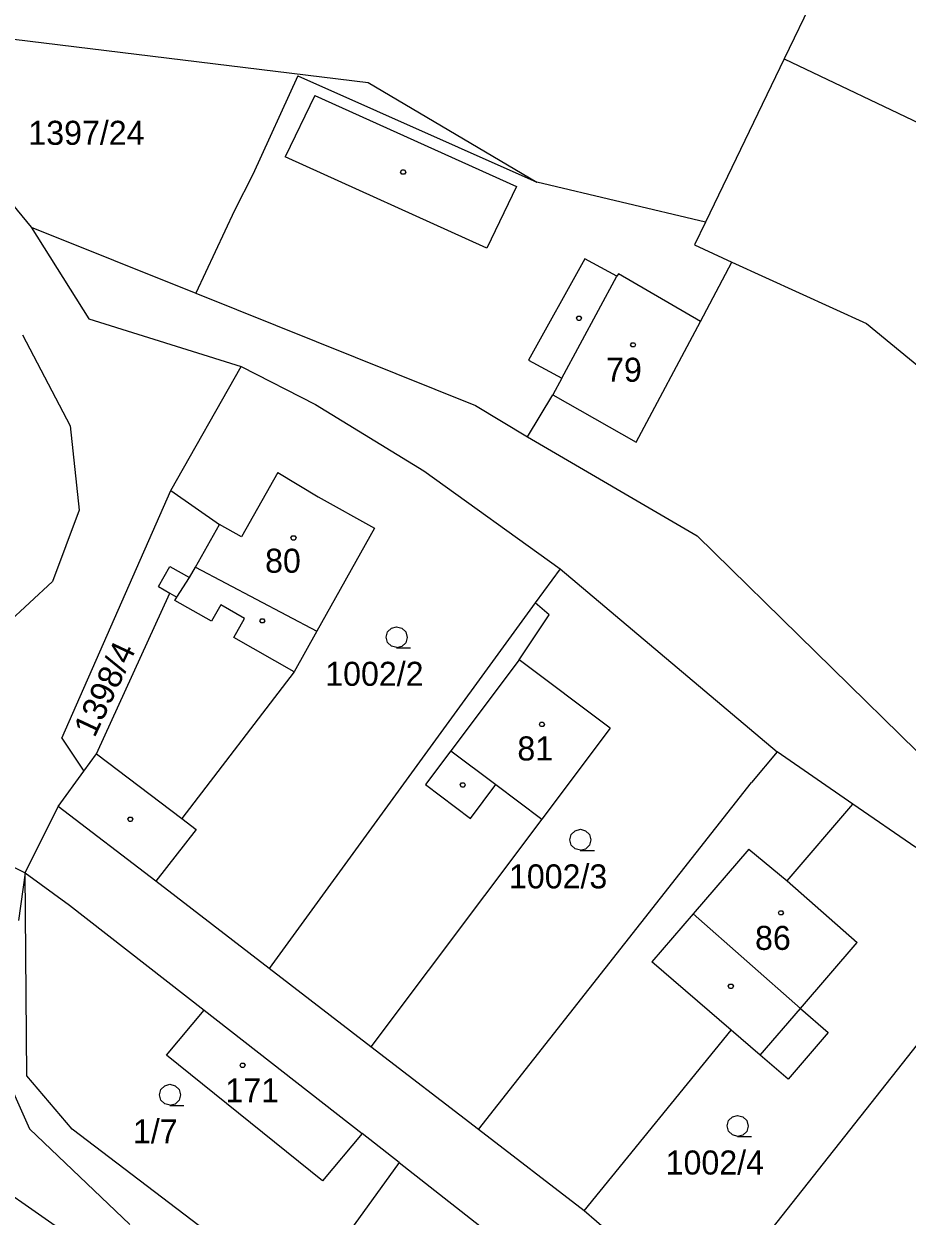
# Model space of a CAD drawing. Extents: x -852001 to -842497, y -1063614 to -1052182.
# Drawn here: x -849249.6 to -849187.1, y -1056339.7 to -1056255.4 of the extents above; entities that cross this region are included whole.
import ezdxf

# ---------------------------------------------------------------- set-up
doc = ezdxf.new("R2010")
doc.units = 0
for name, color, linetype in [('Default', 7, 'Continuous'), ('KN_HRANICE', 7, 'Continuous'), ('KN_KULTURY', 7, 'Continuous'), ('KN_PARCELY', 7, 'Continuous'), ('KN_SLUCKY', 7, 'Continuous')]:
    doc.layers.add(name, color=color, linetype=linetype)

# ---------------------------------------------------------------- blocks, each defined once
blk = doc.blocks.new('304')
at = {"layer": 'Default'}
blk.add_lwpolyline([(0, 0), (-0.38, 0.1), (-0.65, 0.37), (-0.75, 0.74), (-0.65, 1.11), (-0.38, 1.38), (-0.01, 1.48), (0.36, 1.38), (0.63, 1.11), (0.73, 0.73), (0.63, 0.35), (0.36, 0.08), (-0.02, -0.02), (0.98, -0.02)], dxfattribs=at)
blk = doc.blocks.new('402')
at = {"layer": 'Default'}
blk.add_lwpolyline([(0.09, 0.15), (0.18, 0), (0.09, -0.15), (-0.09, -0.15), (-0.18, 0), (-0.09, 0.15), (0.09, 0.15)], dxfattribs=at)

msp = doc.modelspace()

# ---------------------------------------------------------------- linework, layer by layer
at = {"layer": 'KN_HRANICE'}
for p, q in [((-849187.73, -1056241.12), (-849195.81, -1056257.87)), ((-849187.73, -1056241.12), (-849195.81, -1056257.87)), ((-849261.46, -1056255.12), (-849225.25, -1056259.54)), ((-849261.46, -1056255.12), (-849225.25, -1056259.54)), ((-849195.81, -1056257.87), (-849201.39, -1056269.43)), ((-849195.81, -1056257.87), (-849201.39, -1056269.43)), ((-849195.81, -1056257.87), (-849167.34, -1056271.45)), ((-849195.81, -1056257.87), (-849167.34, -1056271.45)), ((-849230.23, -1056259.07), (-849233.42, -1056266.05)), ((-849230.23, -1056259.07), (-849233.42, -1056266.05)), ((-849230.23, -1056259.07), (-849213.31, -1056266.59)), ((-849230.23, -1056259.07), (-849213.31, -1056266.59)), ((-849225.25, -1056259.54), (-849213.31, -1056266.59)), ((-849225.25, -1056259.54), (-849213.31, -1056266.59)), ((-849233.42, -1056266.05), (-849234.71, -1056268.6)), ((-849233.42, -1056266.05), (-849234.71, -1056268.6)), ((-849251.43, -1056266.98), (-849249.09, -1056269.78)), ((-849251.43, -1056266.98), (-849249.09, -1056269.78)), ((-849201.39, -1056269.43), (-849213.31, -1056266.59)), ((-849201.39, -1056269.43), (-849213.31, -1056266.59)), ((-849234.71, -1056268.6), (-849237.45, -1056274.45)), ((-849234.71, -1056268.6), (-849237.45, -1056274.45)), ((-849201.39, -1056269.43), (-849202.16, -1056271.02)), ((-849201.39, -1056269.43), (-849202.16, -1056271.02)), ((-849249.09, -1056269.78), (-849245.03, -1056276.25)), ((-849249.09, -1056269.78), (-849237.45, -1056274.45)), ((-849249.09, -1056269.78), (-849245.03, -1056276.25)), ((-849249.09, -1056269.78), (-849237.45, -1056274.45)), ((-849202.16, -1056271.02), (-849199.51, -1056272.24)), ((-849202.16, -1056271.02), (-849199.51, -1056272.24)), ((-849201.75, -1056276.45), (-849199.51, -1056272.24)), ((-849201.75, -1056276.45), (-849199.51, -1056272.24)), ((-849199.51, -1056272.24), (-849189.99, -1056276.6)), ((-849199.51, -1056272.24), (-849189.99, -1056276.6)), ((-849237.45, -1056274.45), (-849217.67, -1056282.38)), ((-849237.45, -1056274.45), (-849217.67, -1056282.38)), ((-849245.03, -1056276.25), (-849234.23, -1056279.63)), ((-849245.03, -1056276.25), (-849234.23, -1056279.63)), ((-849206.29, -1056284.99), (-849201.75, -1056276.45)), ((-849206.29, -1056284.99), (-849201.75, -1056276.45)), ((-849189.99, -1056276.6), (-849174.78, -1056289.12)), ((-849189.99, -1056276.6), (-849174.78, -1056289.12)), ((-849249.72, -1056277.39), (-849246.35, -1056283.83)), ((-849249.72, -1056277.39), (-849246.35, -1056283.83)), ((-849239.22, -1056288.41), (-849234.23, -1056279.63)), ((-849239.22, -1056288.41), (-849234.23, -1056279.63)), ((-849234.23, -1056279.63), (-849228.99, -1056282.32)), ((-849234.23, -1056279.63), (-849228.99, -1056282.32)), ((-849213.98, -1056284.6), (-849212.18, -1056281.64)), ((-849213.98, -1056284.6), (-849212.18, -1056281.64)), ((-849212.18, -1056281.64), (-849206.29, -1056284.99)), ((-849212.18, -1056281.64), (-849206.29, -1056284.99)), ((-849228.99, -1056282.32), (-849221.32, -1056287)), ((-849228.99, -1056282.32), (-849221.32, -1056287)), ((-849217.67, -1056282.38), (-849213.98, -1056284.6)), ((-849217.67, -1056282.38), (-849213.98, -1056284.6)), ((-849246.35, -1056283.83), (-849245.71, -1056289.79)), ((-849246.35, -1056283.83), (-849245.71, -1056289.79)), ((-849213.98, -1056284.6), (-849201.97, -1056291.61)), ((-849213.98, -1056284.6), (-849201.97, -1056291.61)), ((-849231.64, -1056287.13), (-849234.22, -1056291.69)), ((-849231.64, -1056287.13), (-849234.22, -1056291.69)), ((-849231.64, -1056287.13), (-849228.79, -1056288.86)), ((-849231.64, -1056287.13), (-849228.79, -1056288.86)), ((-849221.32, -1056287), (-849211.67, -1056293.94)), ((-849221.32, -1056287), (-849211.67, -1056293.94)), ((-849246.94, -1056305.93), (-849239.22, -1056288.41)), ((-849246.94, -1056305.93), (-849239.22, -1056288.41)), ((-849239.22, -1056288.41), (-849235.78, -1056290.81)), ((-849239.22, -1056288.41), (-849235.78, -1056290.81)), ((-849228.79, -1056288.86), (-849224.8, -1056291.07)), ((-849228.79, -1056288.86), (-849224.8, -1056291.07)), ((-849245.71, -1056289.79), (-849247.6, -1056294.83)), ((-849245.71, -1056289.79), (-849247.6, -1056294.83)), ((-849237.48, -1056293.82), (-849235.78, -1056290.81)), ((-849237.48, -1056293.82), (-849235.78, -1056290.81)), ((-849234.22, -1056291.69), (-849235.78, -1056290.81)), ((-849234.22, -1056291.69), (-849235.78, -1056290.81)), ((-849224.8, -1056291.07), (-849228.88, -1056298.35)), ((-849224.8, -1056291.07), (-849228.88, -1056298.35)), ((-849161.41, -1056331.37), (-849201.97, -1056291.61)), ((-849161.41, -1056331.37), (-849201.97, -1056291.61)), ((-849240.1, -1056295.2), (-849239.29, -1056293.78)), ((-849240.1, -1056295.2), (-849239.29, -1056293.78)), ((-849239.29, -1056293.78), (-849237.9, -1056294.56)), ((-849239.29, -1056293.78), (-849237.9, -1056294.56)), ((-849237.9, -1056294.56), (-849237.48, -1056293.82)), ((-849237.9, -1056294.56), (-849237.48, -1056293.82)), ((-849211.67, -1056293.94), (-849213.44, -1056296.36)), ((-849211.67, -1056293.94), (-849213.44, -1056296.36)), ((-849211.67, -1056293.94), (-849196.32, -1056306.88)), ((-849211.67, -1056293.94), (-849196.32, -1056306.88)), ((-849247.6, -1056294.83), (-849250.85, -1056297.85)), ((-849247.6, -1056294.83), (-849250.85, -1056297.85)), ((-849244.48, -1056307.03), (-849239.28, -1056295.66)), ((-849244.48, -1056307.03), (-849239.28, -1056295.66)), ((-849240.1, -1056295.2), (-849239.28, -1056295.66)), ((-849240.1, -1056295.2), (-849239.28, -1056295.66)), ((-849213.44, -1056296.36), (-849232.27, -1056322.21)), ((-849213.44, -1056296.36), (-849232.27, -1056322.21)), ((-849212.44, -1056297.19), (-849213.44, -1056296.36)), ((-849212.44, -1056297.19), (-849213.44, -1056296.36)), ((-849214.56, -1056300.37), (-849212.44, -1056297.19)), ((-849214.56, -1056300.37), (-849212.44, -1056297.19)), ((-849228.88, -1056298.35), (-849230.49, -1056301.22)), ((-849228.88, -1056298.35), (-849230.49, -1056301.22)), ((-849208.12, -1056305.21), (-849214.56, -1056300.37)), ((-849208.12, -1056305.21), (-849214.56, -1056300.37)), ((-849230.49, -1056301.22), (-849238.43, -1056311.61)), ((-849230.49, -1056301.22), (-849238.43, -1056311.61)), ((-849208.12, -1056305.21), (-849212.96, -1056311.65)), ((-849208.12, -1056305.21), (-849212.96, -1056311.65)), ((-849246.94, -1056305.93), (-849245.37, -1056308.26)), ((-849246.94, -1056305.93), (-849245.37, -1056308.26)), ((-849245.37, -1056308.26), (-849244.48, -1056307.03)), ((-849245.37, -1056308.26), (-849244.48, -1056307.03)), ((-849196.32, -1056306.88), (-849198.14, -1056309.07)), ((-849196.32, -1056306.88), (-849198.14, -1056309.07)), ((-849190.95, -1056310.59), (-849196.32, -1056306.88)), ((-849190.95, -1056310.59), (-849196.32, -1056306.88)), ((-849247.18, -1056310.75), (-849245.37, -1056308.26)), ((-849247.18, -1056310.75), (-849245.37, -1056308.26)), ((-849217.45, -1056333.6), (-849198.14, -1056309.07)), ((-849217.45, -1056333.6), (-849198.14, -1056309.07)), ((-849249.52, -1056315.45), (-849247.18, -1056310.75)), ((-849249.52, -1056315.45), (-849247.18, -1056310.75)), ((-849240.27, -1056316.03), (-849247.18, -1056310.75)), ((-849240.27, -1056316.03), (-849247.18, -1056310.75)), ((-849195.6, -1056316.01), (-849190.95, -1056310.59)), ((-849195.6, -1056316.01), (-849190.95, -1056310.59)), ((-849186.5, -1056313.66), (-849190.95, -1056310.59)), ((-849186.5, -1056313.66), (-849190.95, -1056310.59)), ((-849238.43, -1056311.61), (-849237.42, -1056312.38)), ((-849238.43, -1056311.61), (-849237.42, -1056312.38)), ((-849212.96, -1056311.65), (-849225.06, -1056327.75)), ((-849212.96, -1056311.65), (-849225.06, -1056327.75)), ((-849237.42, -1056312.38), (-849240.27, -1056316.03)), ((-849237.42, -1056312.38), (-849240.27, -1056316.03)), ((-849252.37, -1056314.02), (-849249.52, -1056315.45)), ((-849252.37, -1056314.02), (-849249.52, -1056315.45)), ((-849249.52, -1056315.45), (-849250, -1056318.83)), ((-849249.52, -1056315.45), (-849250, -1056318.83)), ((-849249.41, -1056329.82), (-849249.52, -1056315.45)), ((-849249.52, -1056315.45), (-849246.38, -1056317.74)), ((-849249.41, -1056329.82), (-849249.52, -1056315.45)), ((-849249.52, -1056315.45), (-849246.38, -1056317.74)), ((-849232.27, -1056322.21), (-849240.27, -1056316.03)), ((-849232.27, -1056322.21), (-849240.27, -1056316.03)), ((-849195.6, -1056316.01), (-849190.65, -1056320.37)), ((-849195.6, -1056316.01), (-849190.65, -1056320.37)), ((-849246.38, -1056317.74), (-849236.86, -1056325.16)), ((-849246.38, -1056317.74), (-849236.86, -1056325.16)), ((-849194.67, -1056325.05), (-849190.65, -1056320.37)), ((-849194.67, -1056325.05), (-849190.65, -1056320.37)), ((-849201.5, -1056346.7), (-849181.26, -1056321.09)), ((-849201.5, -1056346.7), (-849181.26, -1056321.09)), ((-849225.06, -1056327.75), (-849232.27, -1056322.21)), ((-849225.06, -1056327.75), (-849232.27, -1056322.21)), ((-849239.52, -1056328.34), (-849236.86, -1056325.16)), ((-849239.52, -1056328.34), (-849236.86, -1056325.16)), ((-849236.86, -1056325.16), (-849225.69, -1056333.89)), ((-849236.86, -1056325.16), (-849225.69, -1056333.89)), ((-849194.67, -1056325.05), (-849192.7, -1056326.75)), ((-849194.67, -1056325.05), (-849192.7, -1056326.75)), ((-849209.96, -1056339.35), (-849199.56, -1056326.59)), ((-849209.96, -1056339.35), (-849199.56, -1056326.59)), ((-849197.51, -1056328.35), (-849199.56, -1056326.59)), ((-849197.51, -1056328.35), (-849199.56, -1056326.59)), ((-849192.7, -1056326.75), (-849195.53, -1056330.05)), ((-849192.7, -1056326.75), (-849195.53, -1056330.05)), ((-849217.45, -1056333.6), (-849225.06, -1056327.75)), ((-849217.45, -1056333.6), (-849225.06, -1056327.75)), ((-849228.48, -1056337.23), (-849239.52, -1056328.34)), ((-849228.48, -1056337.23), (-849239.52, -1056328.34)), ((-849195.53, -1056330.05), (-849197.51, -1056328.35)), ((-849195.53, -1056330.05), (-849197.51, -1056328.35)), ((-849251.01, -1056329.53), (-849249.23, -1056333.55)), ((-849251.01, -1056329.53), (-849249.23, -1056333.55)), ((-849246.19, -1056333.59), (-849249.41, -1056329.82)), ((-849246.19, -1056333.59), (-849249.41, -1056329.82)), ((-849244.73, -1056342.28), (-849259.75, -1056331.81)), ((-849244.73, -1056342.28), (-849259.75, -1056331.81)), ((-849249.23, -1056333.55), (-849242.11, -1056340.33)), ((-849249.23, -1056333.55), (-849242.11, -1056340.33)), ((-849230.16, -1056345.77), (-849246.19, -1056333.59)), ((-849230.16, -1056345.77), (-849246.19, -1056333.59)), ((-849209.96, -1056339.35), (-849217.45, -1056333.6)), ((-849209.96, -1056339.35), (-849217.45, -1056333.6)), ((-849225.69, -1056333.89), (-849228.48, -1056337.23)), ((-849225.69, -1056333.89), (-849228.48, -1056337.23)), ((-849223.07, -1056335.94), (-849225.69, -1056333.89)), ((-849223.07, -1056335.94), (-849225.69, -1056333.89)), ((-849223.07, -1056335.94), (-849230.16, -1056345.77)), ((-849223.07, -1056335.94), (-849230.16, -1056345.77)), ((-849223.07, -1056335.94), (-849168.88, -1056378.32)), ((-849223.07, -1056335.94), (-849168.88, -1056378.32)), ((-849201.5, -1056346.7), (-849209.96, -1056339.35)), ((-849201.5, -1056346.7), (-849209.96, -1056339.35))]:
    msp.add_line(p, q, dxfattribs=at)
at = {"layer": 'KN_SLUCKY'}
for p, q in [((-849229.04, -1056260.47), (-849231.13, -1056264.79)), ((-849229.04, -1056260.47), (-849231.13, -1056264.79)), ((-849229.04, -1056260.47), (-849214.76, -1056266.9)), ((-849229.04, -1056260.47), (-849214.76, -1056266.9)), ((-849216.86, -1056271.25), (-849231.13, -1056264.79)), ((-849216.86, -1056271.25), (-849231.13, -1056264.79)), ((-849214.76, -1056266.9), (-849216.86, -1056271.25)), ((-849214.76, -1056266.9), (-849216.86, -1056271.25)), ((-849209.93, -1056272.01), (-849213.92, -1056279.18)), ((-849209.93, -1056272.01), (-849213.92, -1056279.18)), ((-849207.65, -1056273.25), (-849209.93, -1056272.01)), ((-849207.65, -1056273.25), (-849209.93, -1056272.01)), ((-849211.54, -1056280.46), (-849207.65, -1056273.25)), ((-849211.54, -1056280.46), (-849207.65, -1056273.25)), ((-849207.55, -1056273.07), (-849207.65, -1056273.25)), ((-849207.55, -1056273.07), (-849207.65, -1056273.25)), ((-849201.75, -1056276.45), (-849207.55, -1056273.07)), ((-849201.75, -1056276.45), (-849207.55, -1056273.07)), ((-849213.92, -1056279.18), (-849211.54, -1056280.46)), ((-849213.92, -1056279.18), (-849211.54, -1056280.46)), ((-849211.54, -1056280.46), (-849212.18, -1056281.64)), ((-849211.54, -1056280.46), (-849212.18, -1056281.64)), ((-849237.48, -1056293.82), (-849228.88, -1056298.35)), ((-849237.48, -1056293.82), (-849228.88, -1056298.35)), ((-849238.79, -1056295.94), (-849237.9, -1056294.56)), ((-849238.79, -1056295.94), (-849237.9, -1056294.56)), ((-849239.28, -1056295.66), (-849238.79, -1056295.94)), ((-849239.28, -1056295.66), (-849238.79, -1056295.94)), ((-849238.93, -1056296.18), (-849238.79, -1056295.94)), ((-849238.93, -1056296.18), (-849238.79, -1056295.94)), ((-849236.33, -1056297.65), (-849238.93, -1056296.18)), ((-849236.33, -1056297.65), (-849238.93, -1056296.18)), ((-849235.68, -1056296.5), (-849236.33, -1056297.65)), ((-849235.68, -1056296.5), (-849236.33, -1056297.65)), ((-849234.01, -1056297.45), (-849235.68, -1056296.5)), ((-849234.01, -1056297.45), (-849235.68, -1056296.5)), ((-849234.77, -1056298.8), (-849234.01, -1056297.45)), ((-849234.77, -1056298.8), (-849234.01, -1056297.45)), ((-849230.49, -1056301.22), (-849234.77, -1056298.8)), ((-849230.49, -1056301.22), (-849234.77, -1056298.8)), ((-849214.56, -1056300.37), (-849219.4, -1056306.81)), ((-849214.56, -1056300.37), (-849219.4, -1056306.81)), ((-849244.48, -1056307.03), (-849238.43, -1056311.61)), ((-849244.48, -1056307.03), (-849238.43, -1056311.61)), ((-849219.4, -1056306.81), (-849221.2, -1056309.2)), ((-849219.4, -1056306.81), (-849221.2, -1056309.2)), ((-849219.4, -1056306.81), (-849216.21, -1056309.21)), ((-849219.4, -1056306.81), (-849216.21, -1056309.21)), ((-849221.2, -1056309.2), (-849218.01, -1056311.6)), ((-849221.2, -1056309.2), (-849218.01, -1056311.6)), ((-849218.01, -1056311.6), (-849216.21, -1056309.21)), ((-849218.01, -1056311.6), (-849216.21, -1056309.21)), ((-849216.21, -1056309.21), (-849212.96, -1056311.65)), ((-849216.21, -1056309.21), (-849212.96, -1056311.65)), ((-849198.33, -1056313.77), (-849202.26, -1056318.34)), ((-849198.33, -1056313.77), (-849202.26, -1056318.34)), ((-849198.33, -1056313.77), (-849195.6, -1056316.01)), ((-849198.33, -1056313.77), (-849195.6, -1056316.01)), ((-849202.26, -1056318.34), (-849205.19, -1056321.75)), ((-849202.26, -1056318.34), (-849205.19, -1056321.75)), ((-849194.67, -1056325.05), (-849202.26, -1056318.34)), ((-849194.67, -1056325.05), (-849202.26, -1056318.34)), ((-849199.56, -1056326.59), (-849205.19, -1056321.75)), ((-849199.56, -1056326.59), (-849205.19, -1056321.75)), ((-849197.51, -1056328.35), (-849194.67, -1056325.05)), ((-849197.51, -1056328.35), (-849194.67, -1056325.05))]:
    msp.add_line(p, q, dxfattribs=at)

# ---------------------------------------------------------------- block references
at = {"layer": 'KN_KULTURY'}
for name, p in [('402', (-849222.78, -1056265.88)), ('402', (-849222.78, -1056265.88)), ('402', (-849210.34, -1056276.22)), ('402', (-849210.34, -1056276.22)), ('402', (-849206.51, -1056278.1)), ('402', (-849206.51, -1056278.1)), ('402', (-849230.54, -1056291.76)), ('402', (-849230.54, -1056291.76)), ('402', (-849232.74, -1056297.62)), ('402', (-849232.74, -1056297.62)), ('304', (-849223.23, -1056299.52)), ('304', (-849223.23, -1056299.52)), ('402', (-849212.96, -1056304.95)), ('402', (-849212.96, -1056304.95)), ('402', (-849218.56, -1056309.23)), ('402', (-849218.56, -1056309.23)), ('402', (-849242.08, -1056311.66)), ('402', (-849242.08, -1056311.66)), ('304', (-849210.23, -1056313.85)), ('304', (-849210.23, -1056313.85)), ('402', (-849196.05, -1056318.28)), ('402', (-849196.05, -1056318.28)), ('402', (-849199.59, -1056323.47)), ('402', (-849199.59, -1056323.47)), ('402', (-849234.14, -1056329.06)), ('402', (-849234.14, -1056329.06)), ('304', (-849239.27, -1056331.89)), ('304', (-849239.27, -1056331.89)), ('304', (-849199.1, -1056334.09)), ('304', (-849199.1, -1056334.09))]:
    msp.add_blockref(name, p, dxfattribs=at)

# ---------------------------------------------------------------- texts
at = {"layer": 'KN_PARCELY'}
for s, p in [('1397/24', (-849249.3, -1056263.95)), ('1397/24', (-849249.3, -1056263.95)), ('79', (-849208.419, -1056280.71)), ('79', (-849208.419, -1056280.71)), ('80', (-849232.549, -1056294.22)), ('80', (-849232.549, -1056294.22)), ('1002/2', (-849228.29, -1056302.22)), ('1002/2', (-849228.29, -1056302.22)), ('81', (-849214.696, -1056307.5)), ('81', (-849214.696, -1056307.5)), ('1002/3', (-849215.29, -1056316.55)), ('1002/3', (-849215.29, -1056316.55)), ('86', (-849197.879, -1056320.9)), ('86', (-849197.879, -1056320.9)), ('171', (-849235.357, -1056331.69)), ('171', (-849235.357, -1056331.69)), ('1/7', (-849241.901, -1056334.59)), ('1/7', (-849241.901, -1056334.59)), ('1002/4', (-849204.2, -1056336.79)), ('1002/4', (-849204.2, -1056336.79))]:
    msp.add_text(s, height=1.7, dxfattribs=at).set_placement(p)
msp.add_text('1398/4', height=1.7, rotation=64.859, dxfattribs=at).set_placement((-849244.617, -1056305.947))
msp.add_text('1398/4', height=1.7, rotation=64.859, dxfattribs=at).set_placement((-849244.617, -1056305.947))

doc.saveas('drawing.dxf')
